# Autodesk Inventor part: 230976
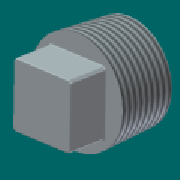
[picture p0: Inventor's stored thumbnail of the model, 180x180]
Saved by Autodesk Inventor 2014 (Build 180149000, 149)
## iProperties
Shininess: 64.0
Length Units: 11272
Angle Units: 11279
Time Units: 11290
Mass Units: 11286
Length Display Precision: 3
Angle Display Precision: 2
Company: Autodesk, Inc.
Created: 2002-05
Part Number: 230976
Material: Stainless Steel, 440C
Description: Fitting; MC-B4-(SS)
Document SubType Name: Modeling
Designer: Autodesk, Inc.
Density: 7.75 g/cm^3
Mass: 22.215 g
Surface Area: 12.0285 cm^2
Volume: 2.86646 cm^3
Appearance: Stainless Steel
Density: 0.0
Volumn: 0.0
Area: 0.0
PropertySet Name: Model Information
Control State: 0
Master: False
Checked Out: False
Last Check In By: JT
Last Check In Date: 2003-06-20
Title: Fitting; MC-B4-(SS)
Author: Autodesk, Inc.
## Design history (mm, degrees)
derived "MC-B.ipt"
body "Solid1"
tag "TaggingFeature2"
feature "Solid1::MC-B.ipt" dims "ScaleForDerivedMember" = 10
